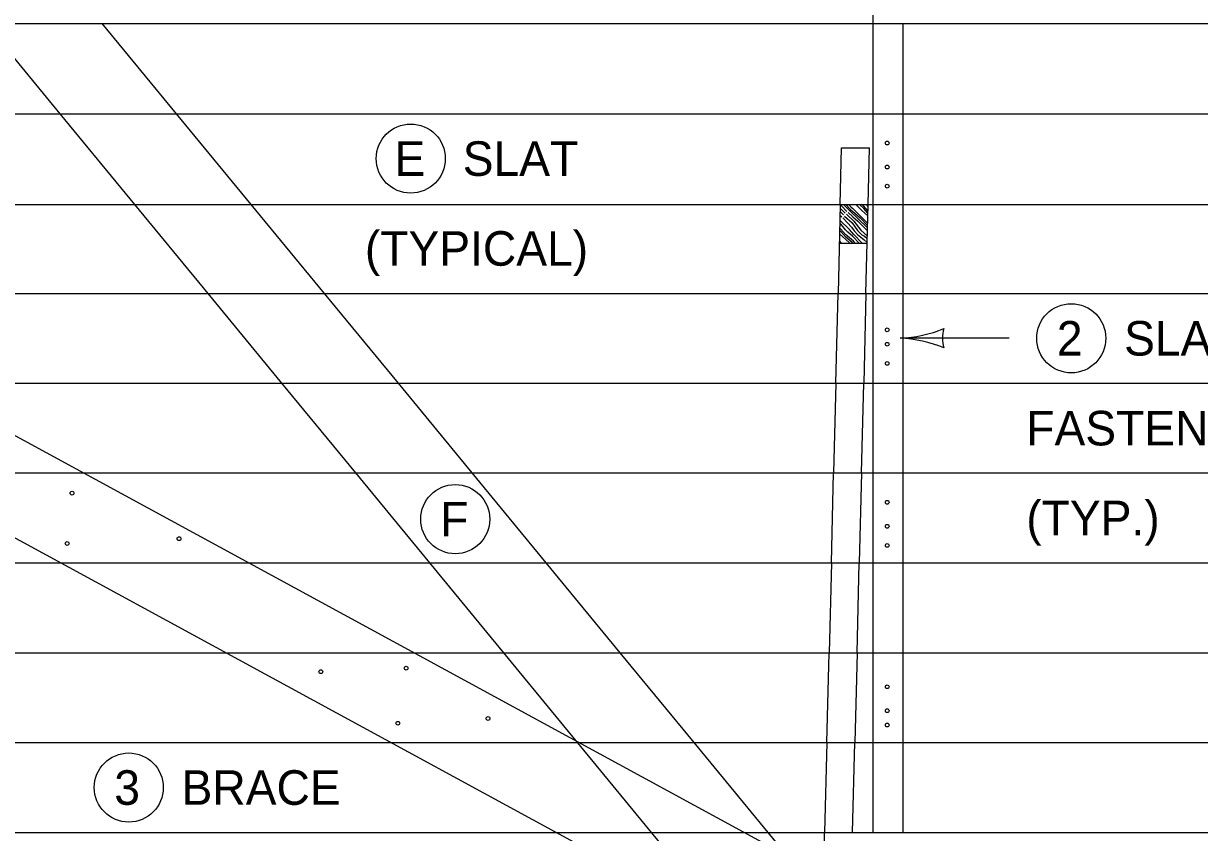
# Model space of a CAD drawing. Extents: x 49991 to 79985, y 47703 to 60542.
# Drawn here: x 50003.842 to 50005.885, y 49995.596 to 49997.001 of the extents above; entities that cross this region are included whole.
import ezdxf

# ---------------------------------------------------------------- set-up
doc = ezdxf.new("R2010")
doc.units = 0
for name, color, linetype in [('Level 1', 7, 'Continuous'), ('Level 2', 7, 'Continuous'), ('Level 3', 7, 'Continuous'), ('Level 4', 7, 'Continuous')]:
    doc.layers.add(name, color=color, linetype=linetype)

msp = doc.modelspace()

# ---------------------------------------------------------------- linework, layer by layer
at = {"layer": 'Level 1'}
for p, q in [((50005.8334, 49995.1946), (50001.4473, 49997.5783)), ((50005.759, 49995.0576), (50001.3728, 49997.4412)), ((50002.5099, 49997.0008), (50006.0719, 49997.0008)), ((50003.7762, 49997.0008), (50003.9051, 49996.8443)), ((50003.9783, 49997.0008), (50004.1072, 49996.8443)), ((50005.3179, 49996.8443), (50005.3179, 49997.0008)), ((50005.3699, 49997.0008), (50005.3699, 49996.8443)), ((50002.7979, 49996.8443), (50006.0719, 49996.8443)), ((50003.0878, 49996.6868), (50006.0719, 49996.6868)), ((50004.0348, 49996.6868), (50004.1621, 49996.5323)), ((50004.237, 49996.6868), (50004.3642, 49996.5323)), ((50005.261, 49996.6868), (50005.2571, 49996.5323)), ((50005.2758, 49996.6776), (50005.2777, 49996.6758)), ((50005.2774, 49996.6792), (50005.2792, 49996.6773)), ((50005.2802, 49996.682), (50005.2821, 49996.6802)), ((50005.3056, 49996.5323), (50005.3095, 49996.6868)), ((50005.3179, 49996.5323), (50005.3179, 49996.6868)), ((50005.3699, 49996.6868), (50005.3699, 49996.5323)), ((50005.2593, 49996.6196), (50005.3078, 49996.6196)), ((50003.372, 49996.5323), (50006.0719, 49996.5323)), ((50003.6591, 49996.3763), (50006.0719, 49996.3763)), ((50004.2905, 49996.3763), (50004.4186, 49996.2208)), ((50004.4927, 49996.3763), (50004.6208, 49996.2208)), ((50005.2533, 49996.3763), (50005.2494, 49996.2208)), ((50005.2978, 49996.2208), (50005.3017, 49996.3763)), ((50005.3179, 49996.2208), (50005.3179, 49996.3763)), ((50005.3699, 49996.3763), (50005.3699, 49996.2208)), ((50003.9452, 49996.2208), (50006.0719, 49996.2208)), ((50001.0799, 49996.0643), (50003.9065, 49996.0643)), ((50004.2332, 49996.0643), (50006.0719, 49996.0643)), ((50004.5474, 49996.0643), (50004.6758, 49995.9083)), ((50004.7497, 49996.0643), (50004.8781, 49995.9083)), ((50005.2455, 49996.0643), (50005.2416, 49995.9083)), ((50005.2901, 49995.9083), (50005.294, 49996.0643)), ((50005.3179, 49995.9083), (50005.3179, 49996.0643)), ((50005.3699, 49996.0643), (50005.3699, 49995.9083)), ((50001.0799, 49995.9083), (50004.1936, 49995.9083)), ((50004.5202, 49995.9083), (50006.0719, 49995.9083)), ((50001.0799, 49995.7523), (50004.4806, 49995.7523)), ((50004.8073, 49995.7523), (50006.0719, 49995.7523)), ((50005.0066, 49995.7523), (50005.1351, 49995.5963)), ((50005.2377, 49995.7523), (50005.2339, 49995.5963)), ((50005.2823, 49995.5963), (50005.2862, 49995.7523)), ((50005.3179, 49995.5963), (50005.3179, 49995.7523)), ((50005.3699, 49995.7523), (50005.3699, 49995.5963)), ((50001.0799, 49995.5963), (50004.7677, 49995.5963)), ((50005.0943, 49995.5963), (50006.0719, 49995.5963))]:
    msp.add_line(p, q, dxfattribs=at)
for points in [[(50005.2608, 49996.6803), (50005.2697, 49996.6715)], [(50005.261, 49996.6864), (50005.2637, 49996.6835), (50005.2727, 49996.6745)], [(50005.2669, 49996.6868), (50005.2758, 49996.6776)], [(50005.2705, 49996.6868), (50005.2774, 49996.6792)], [(50005.2756, 49996.6868), (50005.2802, 49996.682)], [(50005.2821, 49996.6802), (50005.2947, 49996.668), (50005.3086, 49996.6543)], [(50005.3089, 49996.6669), (50005.2987, 49996.6761), (50005.2881, 49996.6868)], [(50005.3091, 49996.6718), (50005.3018, 49996.6798), (50005.2945, 49996.6868)], [(50005.3092, 49996.6753), (50005.3014, 49996.684), (50005.2981, 49996.6868)], [(50005.3094, 49996.6833), (50005.3067, 49996.6868)], [(50005.2605, 49996.6683), (50005.2635, 49996.6653)], [(50005.2607, 49996.6746), (50005.2666, 49996.6684)], [(50005.2992, 49996.6196), (50005.2845, 49996.6345), (50005.2773, 49996.643), (50005.2608, 49996.6589)], [(50005.2654, 49996.6635), (50005.2736, 49996.6548), (50005.2804, 49996.6471), (50005.2849, 49996.6408), (50005.2913, 49996.6341), (50005.2962, 49996.6304), (50005.3026, 49996.6253), (50005.3078, 49996.6205)], [(50005.2685, 49996.6666), (50005.2814, 49996.6546), (50005.2909, 49996.6416), (50005.2986, 49996.634), (50005.303, 49996.6314), (50005.308, 49996.6277)], [(50005.2716, 49996.6697), (50005.2845, 49996.6577), (50005.2965, 49996.6421), (50005.3081, 49996.6319)], [(50005.2746, 49996.6727), (50005.283, 49996.6652), (50005.2916, 49996.6576), (50005.3074, 49996.6418), (50005.3083, 49996.6408)], [(50005.2777, 49996.6758), (50005.3078, 49996.6467), (50005.3084, 49996.6461)], [(50005.2792, 49996.6773), (50005.2861, 49996.6718), (50005.2954, 49996.6635), (50005.3085, 49996.6501)], [(50005.2826, 49996.6196), (50005.2818, 49996.6207), (50005.2709, 49996.6299), (50005.2619, 49996.64), (50005.2598, 49996.6419)], [(50005.287, 49996.6196), (50005.2838, 49996.6231), (50005.2702, 49996.6344), (50005.2615, 49996.6441), (50005.26, 49996.6454)], [(50005.2937, 49996.6196), (50005.2829, 49996.6312), (50005.2741, 49996.6383), (50005.2699, 49996.6428), (50005.2634, 49996.6512), (50005.2602, 49996.6539)], [(50005.2594, 49996.6196), (50005.2593, 49996.6198)], [(50005.2634, 49996.6196), (50005.2594, 49996.6235)], [(50005.2771, 49996.6196), (50005.2763, 49996.6205), (50005.2597, 49996.6355)]]:
    msp.add_lwpolyline(points, dxfattribs=at)
for centre in [(50005.3426, 49996.7933), (50005.3426, 49996.7517), (50005.3426, 49996.7185), (50005.3426, 49996.469), (50005.3426, 49996.444), (50005.3426, 49996.4107), (50003.9263, 49996.1854), (50005.3426, 49996.1695), (50005.3426, 49996.1279), (50004.1122, 49996.1064), (50003.9179, 49996.098), (50005.3426, 49996.0947), (50004.5069, 49995.8816), (50004.3586, 49995.8754), (50005.3426, 49995.8493), (50005.3426, 49995.8077), (50004.4923, 49995.7859), (50004.649, 49995.7942), (50005.3426, 49995.7828)]:
    msp.add_circle(centre, 0.00327, dxfattribs=at)
at = {"layer": 'Level 2'}
for centre in [(50004.5147, 49996.7663), (50005.6624, 49996.4543), (50004.5921, 49996.1403), (50004.0249, 49995.6743)]:
    msp.add_circle(centre, 0.06, dxfattribs=at)
at = {"layer": 'Level 3'}
msp.add_line((50005.5542, 49996.4543), (50005.3651, 49996.4543), dxfattribs=at)
for centre, radius, start, end in [((50005.3536, 49996.687), 0.233, 272.8273, 292.0772), ((50005.3559, 49996.2322), 0.2223, 67.456, 87.6395), ((50005.4933, 49996.4543), 0.0548, 162.1388, 197.8612)]:
    msp.add_arc(centre, radius, start, end, dxfattribs=at)
at = {"layer": 'Level 4'}
for p, q in [((50005.3179, 49997.0008), (50005.3179, 49997.1563)), ((50003.9051, 49996.8443), (50004.0348, 49996.6868)), ((50004.1072, 49996.8443), (50004.237, 49996.6868)), ((50005.3179, 49996.6868), (50005.3179, 49996.8443)), ((50005.3699, 49996.8443), (50005.3699, 49996.6868)), ((50005.261, 49996.6868), (50005.2634, 49996.785)), ((50005.2634, 49996.785), (50005.3119, 49996.785)), ((50005.3095, 49996.6868), (50005.3119, 49996.785)), ((50004.1621, 49996.5323), (50004.2905, 49996.3763)), ((50004.3642, 49996.5323), (50004.4927, 49996.3763)), ((50005.2533, 49996.3763), (50005.2571, 49996.5323)), ((50005.3056, 49996.5323), (50005.3017, 49996.3763)), ((50005.3179, 49996.3763), (50005.3179, 49996.5323)), ((50005.3699, 49996.5323), (50005.3699, 49996.3763)), ((50003.6194, 49996.2203), (50003.9452, 49996.2208)), ((50004.4186, 49996.2208), (50004.5474, 49996.0643)), ((50004.6208, 49996.2208), (50004.7496, 49996.0643)), ((50005.2455, 49996.0643), (50005.2494, 49996.2208)), ((50005.2978, 49996.2208), (50005.294, 49996.0643)), ((50005.3179, 49996.0643), (50005.3179, 49996.2208)), ((50005.3699, 49996.2208), (50005.3699, 49996.0643)), ((50003.9065, 49996.0643), (50003.9065, 49996.0643)), ((50003.9065, 49996.0643), (50004.2332, 49996.0643)), ((50004.1936, 49995.9083), (50004.5202, 49995.9083)), ((50004.6758, 49995.9083), (50005.0667, 49995.4338)), ((50004.8781, 49995.9083), (50005.0066, 49995.7523)), ((50005.2377, 49995.7523), (50005.2416, 49995.9083)), ((50005.2901, 49995.9083), (50005.2862, 49995.7523)), ((50005.3179, 49995.7523), (50005.3179, 49995.9083)), ((50005.3699, 49995.9083), (50005.3699, 49995.7523)), ((50004.4806, 49995.7523), (50004.8073, 49995.7523)), ((50004.7677, 49995.5963), (50005.0943, 49995.5963)), ((50005.1351, 49995.5963), (50005.5206, 49995.1283)), ((50005.2222, 49995.1283), (50005.2339, 49995.5963))]:
    msp.add_line(p, q, dxfattribs=at)

# ---------------------------------------------------------------- texts
at = {"layer": 'Level 2'}
for s, p in [('E', (50004.4867, 49996.7363)), ('SLAT', (50004.6051, 49996.7363)), ('(TYPICAL)', (50004.4351, 49996.5803)), ('2', (50005.6373, 49996.4243)), ('SLAT', (50005.7542, 49996.4243)), ('FASTENING', (50005.5842, 49996.2683)), ('F', (50004.5659, 49996.1103)), ('(TYP.)', (50005.5842, 49996.1123)), ('3', (50003.9997, 49995.6443)), ('BRACE', (50004.1166, 49995.6443))]:
    msp.add_text(s, height=0.06, dxfattribs=at).set_placement(p)

doc.saveas('drawing.dxf')
